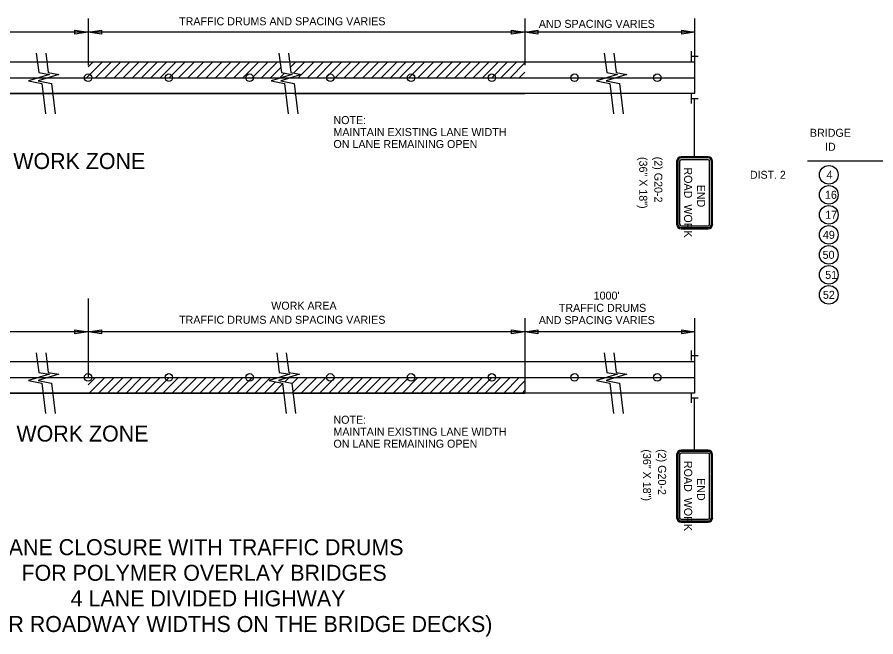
# Model space of a CAD drawing. Extents: x 1930579 to 1938745, y 596452 to 597559.
# Drawn here: x 1937136 to 1937779, y 596540 to 597005 of the extents above; entities that cross this region are included whole.
import ezdxf

# ---------------------------------------------------------------- set-up
doc = ezdxf.new("R2010")
doc.units = 0
for name, color, linetype in [('Default', 7, 'Continuous'), ('P_TC_Signs_Temporary', 7, 'Continuous'), ('R_Annotation', 7, 'Continuous')]:
    doc.layers.add(name, color=color, linetype=linetype)

msp = doc.modelspace()

# ---------------------------------------------------------------- linework, layer by layer
at = {"layer": 'Default'}
for p, q in [((1937188.67, 597003.98), (1937188.67, 596968.94)), ((1937516.16, 597003.98), (1937516.16, 596968.94)), ((1937643.39, 597003.98), (1937643.39, 596947.87)), ((1937178.61, 596992.19), (1937178.61, 596995.21)), ((1937178.61, 596995.21), (1937188.67, 596993.7)), ((1937188.67, 596993.7), (1937198.73, 596995.21)), ((1937198.73, 596995.21), (1937198.73, 596992.19)), ((1937506.1, 596992.19), (1937506.1, 596995.2)), ((1937506.1, 596995.2), (1937516.16, 596993.7)), ((1937516.16, 596993.7), (1937525.82, 596995.15)), ((1937525.82, 596995.15), (1937525.82, 596992.25)), ((1937633.73, 596992.25), (1937633.73, 596995.15)), ((1937633.73, 596995.15), (1937643.39, 596993.7)), ((1937188.67, 596993.7), (1936887.3, 596993.7)), ((1937188.67, 596993.7), (1937178.61, 596992.19)), ((1937516.16, 596993.7), (1937188.67, 596993.7)), ((1937198.73, 596992.19), (1937188.67, 596993.7)), ((1937516.16, 596993.7), (1937506.1, 596992.19)), ((1937525.82, 596992.25), (1937516.16, 596993.7)), ((1937643.39, 596993.7), (1937516.16, 596993.7)), ((1937643.39, 596993.7), (1937633.73, 596992.25)), ((1937640.73, 596979.4), (1937640.73, 596971.92)), ((1937640.84, 596975.68), (1937645.95, 596975.68)), ((1937643.39, 596971.31), (1936696.54, 596971.31)), ((1937187.39, 596959.59), (1937199.11, 596971.31)), ((1937188.67, 596967.77), (1937192.21, 596971.31)), ((1937194.3, 596959.59), (1937206.02, 596971.31)), ((1937201.21, 596959.59), (1937212.92, 596971.31)), ((1937208.11, 596959.59), (1937219.83, 596971.31)), ((1937215.02, 596959.59), (1937226.73, 596971.31)), ((1937221.92, 596959.59), (1937233.64, 596971.31)), ((1937228.83, 596959.59), (1937240.55, 596971.31)), ((1937235.73, 596959.59), (1937247.45, 596971.31)), ((1937242.64, 596959.59), (1937254.36, 596971.31)), ((1937249.54, 596959.59), (1937261.26, 596971.31)), ((1937256.45, 596959.59), (1937268.17, 596971.31)), ((1937263.35, 596959.59), (1937275.07, 596971.31)), ((1937270.26, 596959.59), (1937281.98, 596971.31)), ((1937277.16, 596959.59), (1937288.88, 596971.31)), ((1937284.07, 596959.59), (1937295.79, 596971.31)), ((1937290.97, 596959.59), (1937302.69, 596971.31)), ((1937297.88, 596959.59), (1937309.6, 596971.31)), ((1937304.79, 596959.59), (1937316.5, 596971.31)), ((1937311.69, 596959.59), (1937323.41, 596971.31)), ((1937318.6, 596959.59), (1937330.31, 596971.31)), ((1937340.18, 596967.37), (1937344.13, 596971.31)), ((1937342.74, 596963.02), (1937351.03, 596971.31)), ((1937348.61, 596961.98), (1937357.94, 596971.31)), ((1937353.12, 596959.59), (1937364.84, 596971.31)), ((1937360.03, 596959.59), (1937371.75, 596971.31)), ((1937366.93, 596959.59), (1937378.65, 596971.31)), ((1937373.84, 596959.59), (1937385.56, 596971.31)), ((1937380.74, 596959.59), (1937392.46, 596971.31)), ((1937387.65, 596959.59), (1937399.37, 596971.31)), ((1937394.55, 596959.59), (1937406.27, 596971.31)), ((1937401.46, 596959.59), (1937413.18, 596971.31)), ((1937408.37, 596959.59), (1937420.08, 596971.31)), ((1937415.27, 596959.59), (1937426.99, 596971.31)), ((1937422.18, 596959.59), (1937433.89, 596971.31)), ((1937429.08, 596959.59), (1937440.8, 596971.31)), ((1937435.99, 596959.59), (1937447.71, 596971.31)), ((1937442.89, 596959.59), (1937454.61, 596971.31)), ((1937449.8, 596959.59), (1937461.52, 596971.31)), ((1937456.7, 596959.59), (1937468.42, 596971.31)), ((1937463.61, 596959.59), (1937475.33, 596971.31)), ((1937470.51, 596959.59), (1937482.23, 596971.31)), ((1937477.42, 596959.59), (1937489.14, 596971.31)), ((1937484.32, 596959.59), (1937496.04, 596971.31)), ((1937491.23, 596959.59), (1937502.95, 596971.31)), ((1937498.13, 596959.59), (1937509.85, 596971.31)), ((1937505.04, 596959.59), (1937516.16, 596970.71)), ((1937325.5, 596959.59), (1937333.09, 596967.18)), ((1937332.41, 596959.59), (1937335.81, 596962.99)), ((1937511.95, 596959.59), (1937516.16, 596963.8)), ((1936696.54, 596959.59), (1937643.39, 596959.59)), ((1937346.22, 596959.59), (1937348.52, 596961.89)), ((1937643.39, 596947.87), (1936696.54, 596947.87)), ((1936954.98, 596947.87), (1937223.6, 596947.87)), ((1937162.33, 596947.87), (1937188.46, 596947.87)), ((1937188.46, 596947.87), (1937335.53, 596947.87)), ((1937343, 596947.87), (1937516.16, 596947.87)), ((1937640.73, 596947.64), (1937640.73, 596940.16)), ((1937640.84, 596943.92), (1937645.95, 596943.92)), ((1937188.67, 596794.08), (1937188.67, 596744.24)), ((1937188.67, 596794.08), (1937188.67, 596744.24)), ((1937188.67, 596782.21), (1937188.67, 596734.89)), ((1937516.16, 596779.28), (1937516.16, 596723.17)), ((1937516.16, 596779.28), (1937516.16, 596744.24)), ((1937643.39, 596779.28), (1937643.39, 596723.17)), ((1937188.67, 596769), (1936887.3, 596769)), ((1937178.61, 596767.49), (1937178.61, 596770.51)), ((1937178.61, 596770.51), (1937188.67, 596769)), ((1937188.67, 596769), (1937178.61, 596767.49)), ((1937188.67, 596769), (1937198.73, 596770.51)), ((1937516.16, 596769), (1937188.67, 596769)), ((1937198.73, 596767.49), (1937188.67, 596769)), ((1937198.73, 596770.51), (1937198.73, 596767.49)), ((1937506.1, 596767.49), (1937506.1, 596770.5)), ((1937506.1, 596770.5), (1937516.16, 596769)), ((1937516.16, 596769), (1937506.1, 596767.49)), ((1937516.16, 596769), (1937525.82, 596770.45)), ((1937525.82, 596767.55), (1937516.16, 596769)), ((1937643.39, 596769), (1937516.16, 596769)), ((1937525.82, 596770.45), (1937525.82, 596767.55)), ((1937633.73, 596767.55), (1937633.73, 596770.45)), ((1937633.73, 596770.45), (1937643.39, 596769)), ((1937643.39, 596769), (1937633.73, 596767.55)), ((1937640.73, 596754.94), (1937640.73, 596747.46)), ((1937640.84, 596751.22), (1937645.95, 596751.22)), ((1937643.39, 596746.61), (1936696.54, 596746.61)), ((1936696.54, 596734.89), (1937643.39, 596734.89)), ((1937188.67, 596729.26), (1937194.3, 596734.89)), ((1937189.49, 596723.17), (1937201.21, 596734.89)), ((1937196.39, 596723.17), (1937208.11, 596734.89)), ((1937203.3, 596723.17), (1937215.02, 596734.89)), ((1937210.2, 596723.17), (1937221.92, 596734.89)), ((1937217.11, 596723.17), (1937228.83, 596734.89)), ((1937224.01, 596723.17), (1937235.73, 596734.89)), ((1937230.92, 596723.17), (1937242.64, 596734.89)), ((1937237.82, 596723.17), (1937249.54, 596734.89)), ((1937244.73, 596723.17), (1937256.45, 596734.89)), ((1937251.63, 596723.17), (1937263.35, 596734.89)), ((1937258.54, 596723.17), (1937270.26, 596734.89)), ((1937265.45, 596723.17), (1937277.16, 596734.89)), ((1937272.35, 596723.17), (1937284.07, 596734.89)), ((1937279.26, 596723.17), (1937290.97, 596734.89)), ((1937286.16, 596723.17), (1937297.88, 596734.89)), ((1937293.07, 596723.17), (1937304.79, 596734.89)), ((1937299.97, 596723.17), (1937311.69, 596734.89)), ((1937306.88, 596723.17), (1937318.6, 596734.89)), ((1937313.78, 596723.17), (1937325.5, 596734.89)), ((1937320.69, 596723.17), (1937329.13, 596731.61)), ((1937336.07, 596731.64), (1937339.31, 596734.89)), ((1937341.4, 596723.17), (1937353.12, 596734.89)), ((1937341.5, 596730.17), (1937346.22, 596734.89)), ((1937348.31, 596723.17), (1937360.03, 596734.89)), ((1937355.21, 596723.17), (1937366.93, 596734.89)), ((1937362.12, 596723.17), (1937373.84, 596734.89)), ((1937369.03, 596723.17), (1937380.74, 596734.89)), ((1937375.93, 596723.17), (1937387.65, 596734.89)), ((1937382.84, 596723.17), (1937394.55, 596734.89)), ((1937389.74, 596723.17), (1937401.46, 596734.89)), ((1937396.65, 596723.17), (1937408.37, 596734.89)), ((1937403.55, 596723.17), (1937415.27, 596734.89)), ((1937410.46, 596723.17), (1937422.18, 596734.89)), ((1937417.36, 596723.17), (1937429.08, 596734.89)), ((1937424.27, 596723.17), (1937435.99, 596734.89)), ((1937431.17, 596723.17), (1937442.89, 596734.89)), ((1937438.08, 596723.17), (1937449.8, 596734.89)), ((1937444.98, 596723.17), (1937456.7, 596734.89)), ((1937451.89, 596723.17), (1937463.61, 596734.89)), ((1937458.79, 596723.17), (1937470.51, 596734.89)), ((1937465.7, 596723.17), (1937477.42, 596734.89)), ((1937472.61, 596723.17), (1937484.32, 596734.89)), ((1937479.51, 596723.17), (1937491.23, 596734.89)), ((1937486.42, 596723.17), (1937498.13, 596734.89)), ((1937493.32, 596723.17), (1937505.04, 596734.89)), ((1937500.23, 596723.17), (1937511.95, 596734.89)), ((1937507.13, 596723.17), (1937516.16, 596732.19)), ((1937327.59, 596723.17), (1937334.41, 596729.99)), ((1937514.04, 596723.17), (1937516.16, 596725.29)), ((1937643.39, 596723.17), (1936696.54, 596723.17)), ((1936954.98, 596723.17), (1937223.6, 596723.17)), ((1937162.33, 596723.17), (1937188.46, 596723.17)), ((1937188.46, 596723.17), (1937335.53, 596723.17)), ((1937334.5, 596723.17), (1937335.15, 596723.82)), ((1937343, 596723.17), (1937516.16, 596723.17)), ((1937640.73, 596723.18), (1937640.73, 596715.7)), ((1937640.84, 596719.46), (1937645.95, 596719.46))]:
    msp.add_line(p, q, dxfattribs=at)
for points in [[(1937149.85, 596978.04), (1937151.68, 596963.38), (1937159.74, 596961.96), (1937144.09, 596957.22), (1937154.05, 596955.32), (1937156.8, 596932.48)], [(1937156.96, 596978.04), (1937158.79, 596963.38), (1937166.85, 596961.96), (1937151.2, 596957.22), (1937161.16, 596955.32), (1937163.91, 596932.48)], [(1937331.74, 596978.04), (1937333.57, 596963.38), (1937341.63, 596961.96), (1937325.98, 596957.22), (1937335.94, 596955.32), (1937338.69, 596932.48)], [(1937338.85, 596978.04), (1937340.68, 596963.38), (1937348.74, 596961.96), (1937333.09, 596957.22), (1937343.05, 596955.32), (1937345.8, 596932.48)], [(1937575.66, 596978.04), (1937577.49, 596963.38), (1937585.55, 596961.96), (1937569.9, 596957.22), (1937579.86, 596955.32), (1937582.61, 596932.48)], [(1937582.77, 596978.04), (1937584.6, 596963.38), (1937592.66, 596961.96), (1937577.01, 596957.22), (1937586.97, 596955.32), (1937589.72, 596932.48)], [(1937149.85, 596753.34), (1937151.68, 596738.68), (1937159.74, 596737.26), (1937144.09, 596732.52), (1937154.05, 596730.62), (1937156.8, 596707.78)], [(1937156.96, 596753.34), (1937158.79, 596738.68), (1937166.85, 596737.26), (1937151.2, 596732.52), (1937161.16, 596730.62), (1937163.91, 596707.78)], [(1937330.13, 596753.34), (1937331.97, 596738.68), (1937340.03, 596737.26), (1937324.38, 596732.52), (1937334.34, 596730.62), (1937337.08, 596707.78)], [(1937337.25, 596753.34), (1937339.08, 596738.68), (1937347.14, 596737.26), (1937331.49, 596732.52), (1937341.45, 596730.62), (1937344.2, 596707.78)], [(1937575.66, 596753.34), (1937577.49, 596738.68), (1937585.55, 596737.26), (1937569.9, 596732.52), (1937579.86, 596730.62), (1937582.61, 596707.78)], [(1937582.77, 596753.34), (1937584.6, 596738.68), (1937592.66, 596737.26), (1937577.01, 596732.52), (1937586.97, 596730.62), (1937589.72, 596707.78)]]:
    msp.add_lwpolyline(points, dxfattribs=at)
for centre in [(1937188.67, 596959.59), (1937249.21, 596959.59), (1937309.75, 596959.59), (1937370.29, 596959.59), (1937430.82, 596959.59), (1937491.36, 596959.59), (1937553.36, 596959.59), (1937615.36, 596959.59), (1937188.67, 596734.89), (1937249.21, 596734.89), (1937309.75, 596734.89), (1937370.29, 596734.89), (1937430.82, 596734.89), (1937491.36, 596734.89), (1937553.36, 596734.89), (1937615.36, 596734.89)]:
    msp.add_circle(centre, 2.8, dxfattribs=at)
at = {"layer": 'P_TC_Signs_Temporary'}
for p, q in [((1937653.52, 596900.35), (1937633.27, 596900.35)), ((1937653.52, 596899.42), (1937633.27, 596899.42)), ((1937653.52, 596898.1), (1937633.27, 596898.1)), ((1937629.89, 596896.98), (1937629.89, 596849.73)), ((1937630.83, 596896.98), (1937630.83, 596849.73)), ((1937632.14, 596896.98), (1937632.14, 596849.73)), ((1937654.64, 596849.73), (1937654.64, 596896.98)), ((1937655.96, 596849.73), (1937655.96, 596896.98)), ((1937656.89, 596849.73), (1937656.89, 596896.98)), ((1937633.27, 596848.6), (1937653.52, 596848.6)), ((1937633.27, 596847.29), (1937653.52, 596847.29)), ((1937633.27, 596846.35), (1937653.52, 596846.35)), ((1937653.52, 596680.33), (1937633.27, 596680.33)), ((1937653.52, 596679.39), (1937633.27, 596679.39)), ((1937629.89, 596676.95), (1937629.89, 596629.7)), ((1937630.83, 596676.95), (1937630.83, 596629.7)), ((1937632.14, 596676.95), (1937632.14, 596629.7)), ((1937653.52, 596678.08), (1937633.27, 596678.08)), ((1937654.64, 596629.7), (1937654.64, 596676.95)), ((1937655.96, 596629.7), (1937655.96, 596676.95)), ((1937656.89, 596629.7), (1937656.89, 596676.95)), ((1937633.27, 596628.58), (1937653.52, 596628.58)), ((1937633.27, 596627.26), (1937653.52, 596627.26)), ((1937633.27, 596626.33), (1937653.52, 596626.33))]:
    msp.add_line(p, q, dxfattribs=at)
for centre, radius, start, end in [((1937633.27, 596896.98), 3.37, 90, 180), ((1937633.27, 596896.98), 2.44, 90, 180), ((1937633.27, 596896.98), 1.13, 90, 180), ((1937653.52, 596896.98), 3.37, 360, 90), ((1937653.52, 596896.98), 2.44, 360, 90), ((1937653.52, 596896.98), 1.13, 360, 90), ((1937633.27, 596849.73), 3.37, 180, 270), ((1937633.27, 596849.73), 2.44, 180, 270), ((1937633.27, 596849.73), 1.13, 180, 270), ((1937653.52, 596849.73), 2.44, 270, 360), ((1937653.52, 596849.73), 1.13, 270, 360), ((1937653.52, 596849.73), 3.38, 270, 360), ((1937633.27, 596676.95), 3.37, 90, 180), ((1937633.27, 596676.95), 2.44, 90, 180), ((1937653.52, 596676.95), 3.37, 360, 90), ((1937653.52, 596676.95), 2.44, 360, 90), ((1937633.27, 596676.95), 1.13, 90, 180), ((1937653.52, 596676.95), 1.13, 360, 90), ((1937633.27, 596629.7), 3.37, 180, 270), ((1937633.27, 596629.7), 2.44, 180, 270), ((1937633.27, 596629.7), 1.13, 180, 270), ((1937653.52, 596629.7), 2.44, 270, 360), ((1937653.52, 596629.7), 1.13, 270, 360), ((1937653.52, 596629.7), 3.38, 270, 360)]:
    msp.add_arc(centre, radius, start, end, dxfattribs=at)
at = {"layer": 'R_Annotation'}
for p, q in [((1937643.39, 596900.35), (1937643.39, 596943.92)), ((1937728.11, 596897.28), (1938205.34, 596897.28)), ((1937643.39, 596680.33), (1937643.39, 596719.46))]:
    msp.add_line(p, q, dxfattribs=at)
for centre in [(1937743.96, 596886.78), (1937743.96, 596871.78), (1937743.96, 596856.78), (1937743.96, 596841.78), (1937743.96, 596826.78), (1937743.96, 596811.78), (1937743.96, 596796.78)]:
    msp.add_circle(centre, 7, dxfattribs=at)

# ---------------------------------------------------------------- texts
at = {"layer": 'Default'}
for s, height, p in [('TRAFFIC DRUMS AND SPACING VARIES', 6, (1937256.89, 596998.9)), ('AND SPACING VARIES', 6, (1937526.56, 596996.99)), ('DIVERSION FOR LT. LANE WORK ZONE', 12, (1936927.5, 596891.14)), ("1000'", 6, (1937567.68, 596793.22)), ('WORK AREA', 6, (1937325.95, 596785.65)), ('TRAFFIC DRUMS ', 6, (1937541.56, 596784.03)), ('TRAFFIC DRUMS AND SPACING VARIES', 6, (1937256.88, 596775.09)), ('AND SPACING VARIES', 6, (1937526.56, 596774.81)), ('DIVERSION FOR RT. LANE WORK ZONE', 12, (1936927.21, 596686.77)), ('LANE CLOSURE WITH TRAFFIC DRUMS', 12, (1937120.24, 596601.57)), ('FOR POLYMER OVERLAY BRIDGES', 12, (1937138.76, 596582.37)), ('4 LANE DIVIDED HIGHWAY', 12, (1937175.61, 596563.17)), ('(VAR. CLEAR ROADWAY WIDTHS ON THE BRIDGE DECKS)', 12, (1937039.74, 596543.97))]:
    msp.add_text(s, height=height, rotation=360, dxfattribs=at).set_placement(p)
at = {"layer": 'P_TC_Signs_Temporary'}
for s, p in [('ROAD  WORK', (1937635.52, 596892.31)), ('END', (1937645.27, 596879.38)), ('ROAD  WORK', (1937635.52, 596672.29)), ('END', (1937645.27, 596659.36))]:
    msp.add_text(s, height=6, rotation=270, dxfattribs=at).set_placement(p)
at = {"layer": 'R_Annotation'}
for s, height, rotation, p in [('NOTE:', 6, 360, (1937372.6, 596924.82)), ('MAINTAIN EXISTING LANE WIDTH', 6, 360, (1937372.6, 596915.84)), ('BRIDGE', 6, 360, (1937729.78, 596915.28)), ('ON LANE REMAINING OPEN', 6, 360, (1937372.6, 596906.86)), ('ID', 6, 360, (1937741.1, 596904.78)), ('(36" X 18")', 6, 270, (1937601.85, 596900.15)), ('(2) G20-2', 6, 270, (1937613.15, 596900.35)), ('DIST. 2', 5.925, 360, (1937684.87, 596883.85)), ('4', 6, 360, (1937742.26, 596883.78)), ('16', 6, 360, (1937741.1, 596868.78)), ('17', 6, 360, (1937741.26, 596853.78)), ('49', 6, 360, (1937739.54, 596838.78)), ('50', 6, 360, (1937739.3, 596823.78)), ('51', 6, 360, (1937741.26, 596808.78)), ('52', 6, 360, (1937739.56, 596793.78)), ('NOTE:', 6, 360, (1937372.6, 596700.12)), ('MAINTAIN EXISTING LANE WIDTH', 6, 360, (1937372.6, 596691.14)), ('ON LANE REMAINING OPEN', 6, 360, (1937372.6, 596682.16)), ('(36" X 18")', 6, 270, (1937604.68, 596680.9)), ('(2) G20-2', 6, 270, (1937615.99, 596681.1))]:
    msp.add_text(s, height=height, rotation=rotation, dxfattribs=at).set_placement(p)

doc.saveas('drawing.dxf')
